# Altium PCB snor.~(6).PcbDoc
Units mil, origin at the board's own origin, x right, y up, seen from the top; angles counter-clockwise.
Board outline 6000 x 4000 mil, 2 copper layers (Top Layer, Bottom Layer); 54 components, 39 nets, 160 pads, 0 vias.
Unrouted connection lines stored in the file: 82.
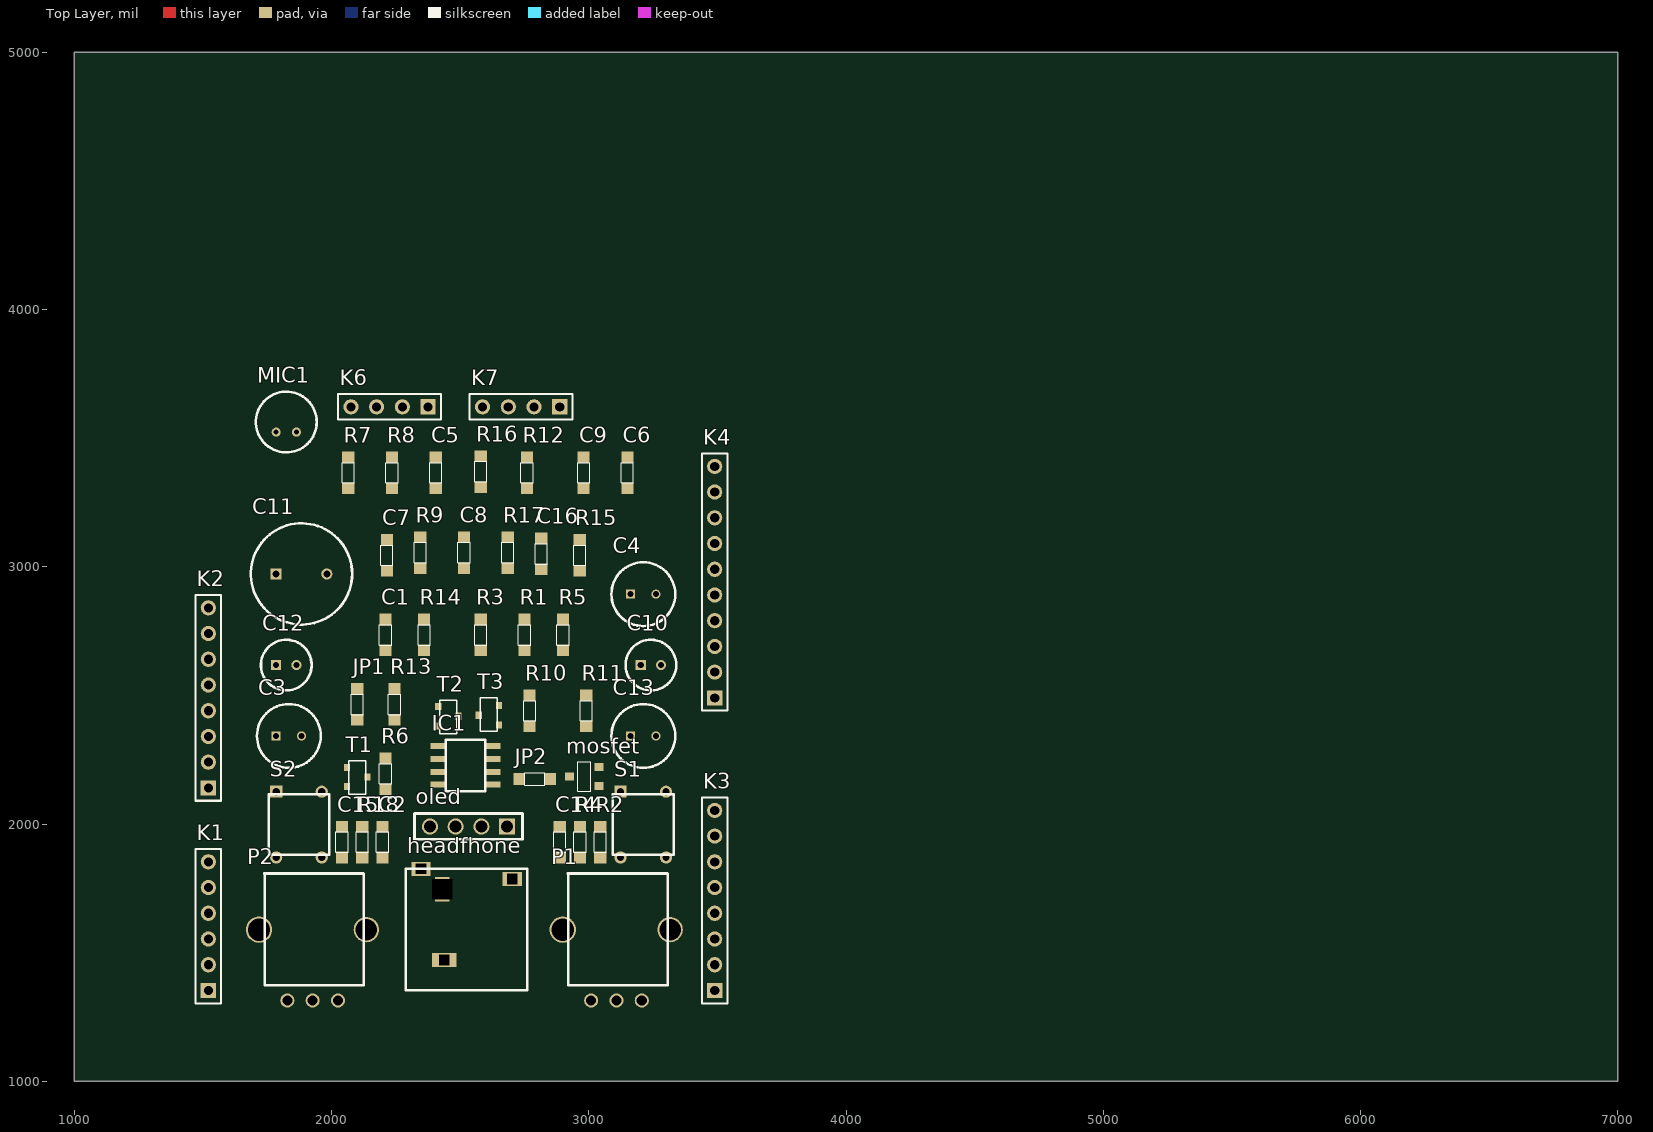
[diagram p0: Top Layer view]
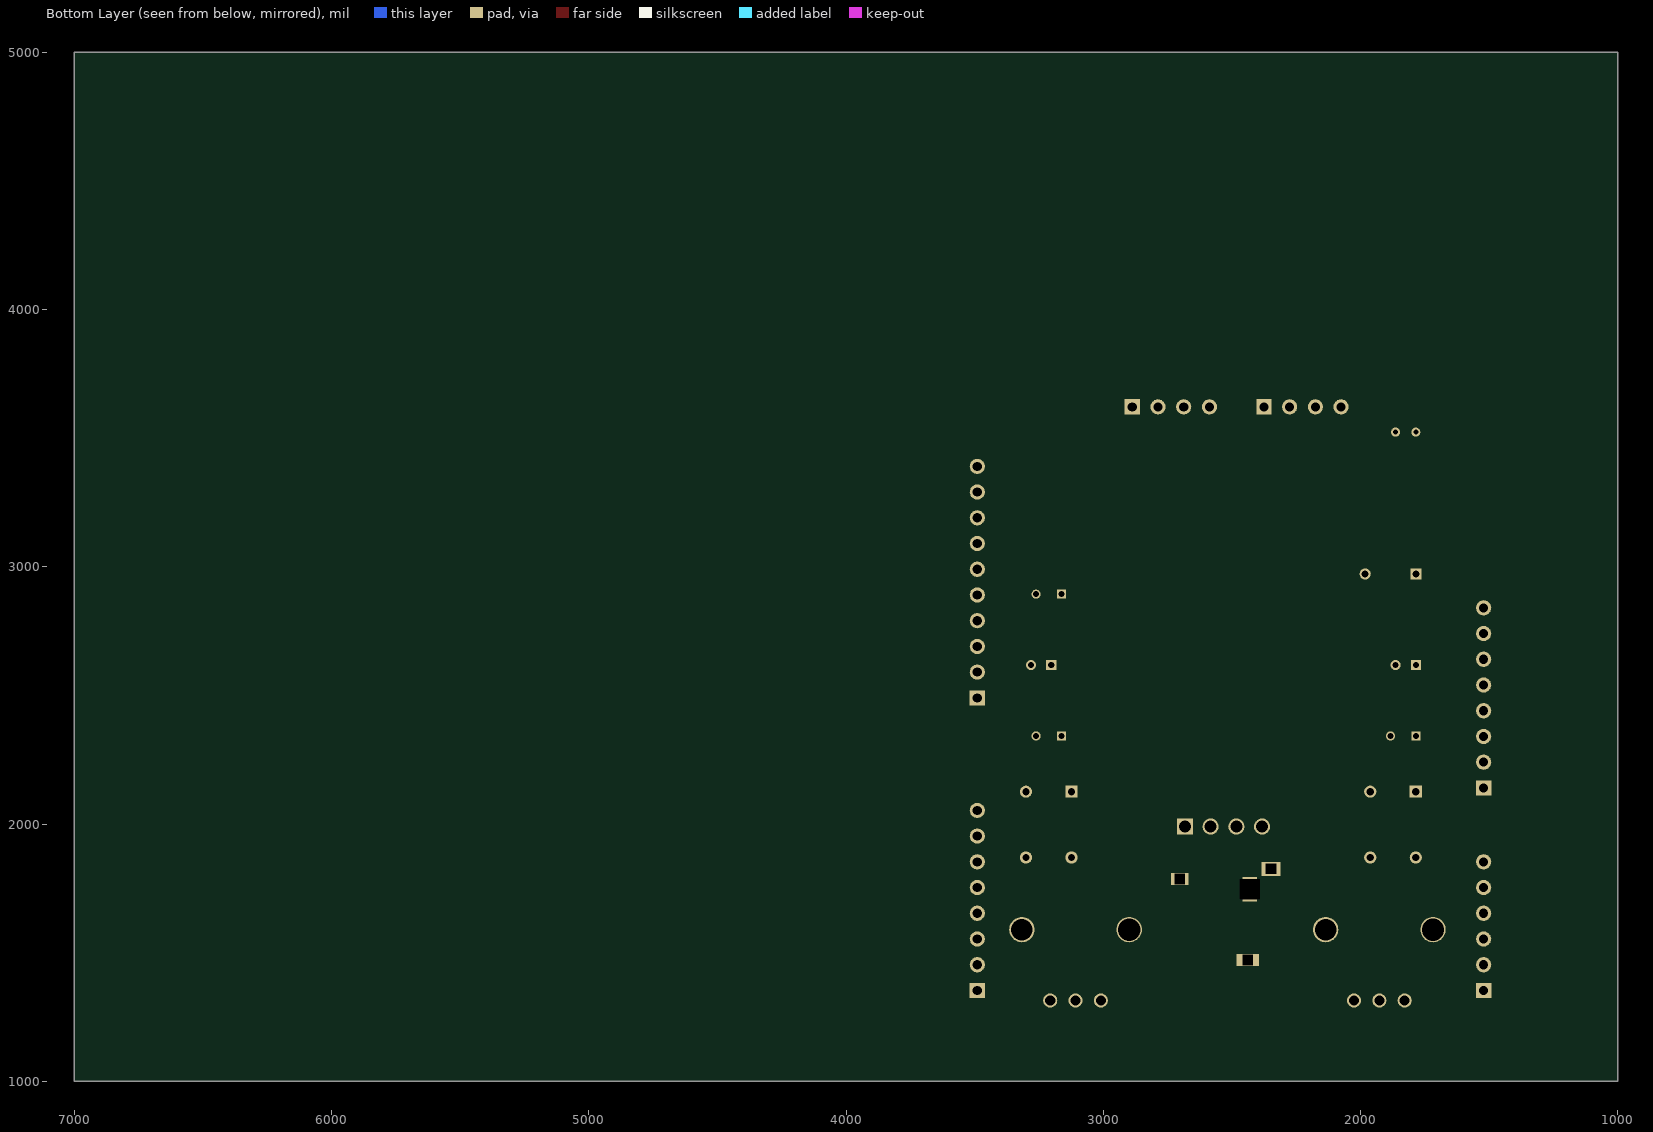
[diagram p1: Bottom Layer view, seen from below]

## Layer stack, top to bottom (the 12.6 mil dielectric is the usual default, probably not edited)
Top Solder: solder mask 0.4, Solder Resist, Dk 3.5
Top Layer: signal copper 1.4
Dielectric 1: dielectric 12.6, FR-4, Dk 4.8
Bottom Layer: signal copper 1.4
Bottom Solder: solder mask 0.4, Solder Resist, Dk 3.5

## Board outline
1000,1000 7000,1000 7000,5000 1000,5000

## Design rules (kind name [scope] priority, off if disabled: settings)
Clearance [All] p1: gap=10 ignorepadtopadclearanceinfootprint=FALSE except(0: Arc-Hole Track-Hole SMDPad-Hole THPad-Hole Via-Hole Fill-Hole Poly-Hole Region-Hole Text-Hole)
PolygonConnect [All] p1: connectstyle=Relief reliefconductorwidth=10 reliefentries=4 polygonreliefangle="90 Angle" airgapwidth=10
RoomDefinition snor_shield_sheet [InComponentClass('snor_shield_sheet')] p1: confinementstyle=ConfineIn formatcopy=TRUE lockcomponents=FALSE outline 8280,1385 21060,1385 21060,2505 8280,2505
RoutingVias [All] p1: holewidth=28 width=50 viastyle="Through Hole" minholewidth=28 minwidth=50 maxholewidth=28 maxwidth=50
SolderMaskExpansion [All] p1: expansion=4 istentingtop=FALSE
Width [All] p1: maxlimit=10 minlimit=10 preferedwidth=10
30 further rules are at their usual default settings.

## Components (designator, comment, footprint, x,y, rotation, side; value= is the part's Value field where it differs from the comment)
C1 "Capitor" "SMD 0805" 2210,2675 r90 top value=1µF
C2 "Capitor" "SMD 0805" 2198.19,1869.76 r90 top value=100nF
C3 "Cap Pol1" "elektor trans 2" 1784.8,2342.2 r0 top value=47µF/16V
C4 "Cap Pol1" "elektor trans 2" 3162.76,2893.39 r0 top value=47µF/16V
C5 "Capitor" "SMD 0805" 2405,3305 r90 top value=100pF
C6 "Capitor" "SMD 0805" 3150,3305 r90 top value=100pF
C7 "Capitor" "SMD 0805" 2215,2985 r90 top value=1nF
C8 "Capitor" "SMD 0805" 2515,2995 r90 top value=1µF
C9 "Capitor" "SMD 0805" 2980,3305 r90 top value=47nF
C10 "Cap Pol1" "elecktor trans 1" 3202.13,2617.8 r0 top value=10µF/16V
C11 "Cap Pol1" "elektor trans 3" 1784.8,2972.13 r0 top value=220µF/16V
C12 "Cap Pol1" "elecktor trans 1" 1784.8,2617.8 r0 top value=10µF/16V
C13 "Cap Pol1" "elektor trans 2" 3162.76,2342.2 r0 top value=47µF/16V
C14 "Cap" "SMD 0805" 2887.17,1869.76 r90 top value=100nF
C15 "Capitor" "SMD 0805" 2040.71,1869.76 r90 top value=100nF
C16 "Capitor" "SMD 0805" 2815,2990 r90 top value=100nF
headfhone "K-JACK-STEREO-3.5MM" adioplug3.5mm 2702.2,1786.02 r180 top
IC1 "LM386M-1/NOPB" LM386M-1/NOPB 2414.72,2302.83 r0 top
JP1 "Res2" "SMD 0805" 2100,2525.08 r270 top value=0Ohm
JP2 "Res2" "SMD 0805" 2850.08,2175 r180 top value=0Ohm
K1 "Header 6" HDR1X6 1521.1,1352.95 r90 top
K2 "Header 8" HDR1X8 1521.1,2140.35 r90 top
K3 "Header 8" HDR1X8 3489.61,1352.95 r90 top
K4 "Header 10" HDR1X10 3489.61,2490.35 r90 top
K6 "Header 4" HDR1X4 2375.35,3621.73 r180 top
K7 "Header 4" HDR1X4 2887.17,3621.73 r180 top
MIC1 "Mic2" "Electret Condenser Microphone" 1784.8,3523.31 r0 top
mosfet "power MOSFET" "power mosfet" 2925,2184.72 r90 top
oled "1X4 socked" "oled scherm" 2682.52,1990 r180 top
P1 "Res Adj2" potmeter 2899.06,1589.17 r0 top value=100k
P2 "Res Adj2" potmeter 1717.95,1589.17 r0 top value=10K
R1 "weerstand" "SMD 0805" 2750,2675 r90 top value=27K
R2 "weerstand" "SMD 0805" 3044.65,1869.76 r90 top value=15K
R3 "weerstand" "SMD 0805" 2580,2675 r90 top value=27K
R4 "weerstand" "SMD 0805" 2965.91,1869.76 r90 top value=1K2
R5 "weerstand" "SMD 0805" 2900,2675 r90 top value=10K
R6 "weerstand" "SMD 0805" 2210,2134.92 r90 top value=680Ohm
R7 "weerstand" "SMD 0805" 2065,3305 r90 top value=10K
R8 "weerstand" "SMD 0805" 2235,3305 r90 top value=10K
R9 "weerstand" "SMD 0805" 2345,2995 r90 top value=10K
R10 "weerstand" "SMD 0805" 2770,2380 r90 top value=180K
R11 "weerstand" "SMD 0805" 2990,2380 r90 top value=180K
R12 "weerstand" "SMD 0805" 2760,3305 r90 top value=10K
R13 "weerstand" "SMD 0805" 2245,2404.92 r90 top value=1K
R14 "weerstand" "SMD 0805" 2360,2675 r90 top value=100K
R15 "weerstand" "SMD 0805" 2965,2985 r90 top value=10Ohm
R16 "weerstand" "SMD 0805" 2580,3309.92 r90 top value=1K
R17 "Res2" "SMD 0805" 2685,2995 r90 top value=100K
R18 "weerstand" "SMD 0805" 2119.45,1869.76 r90 top value=10Ohm
S1 "SW-PB" switch 3123.39,2125.67 r0 top
S2 "SW-PB" switch 1784.8,2125.67 r0 top
T1 "BC847C" "bipolar BjT" 2060.39,2145.35 r90 top
T2 "BC847C" "bipolar BjT" 2414.72,2381.57 r90 top
T3 "BC847C" "bipolar BjT" 2650.94,2460.32 r270 top

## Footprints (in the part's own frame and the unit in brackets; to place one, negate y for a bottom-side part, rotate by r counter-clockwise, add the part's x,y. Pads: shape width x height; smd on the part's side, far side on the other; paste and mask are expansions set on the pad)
adioplug3.5mm [mm]
  rect 1.4x2.4 hole 2 square: B(6.9,1)
  rect 1.9x1.4 hole 1 square: R(9,-1)
  rect 2.4x1.4 / inner rect 2.2x1.27 / far side rect 2.2x1.2 hole 1 square: S(6.7,8)
  rect 1.9x1.4 / inner rect 2.54x1.27 / far side rect 1.7x1.2 hole 1 square: T(0,0)
  silkscreen extent -1.5,-1 10.5,11
"bipolar BjT" [mm]
  rect 0.7x0.6 smd: 1(0,0) 3(0.95,-2) 4(1.9,0)
  silkscreen extent -0.76,-1.85 2.54,-0.15
"elecktor trans 1" [mm]
  rect 1x1 hole 0.6: 1(0,0)
  round 1 hole 0.6: 2(2,0)
  silkscreen extent -1.5,-2.5 3.5,2.5
"Electret Condenser Microphone" [mm]
  round 0.9 hole 0.5: 1(0,0) 2(2,0)
  silkscreen extent -2,-2 4,4
"elektor trans 2" [mm]
  rect 0.9x0.9 hole 0.6: 1(0,0)
  round 0.9 hole 0.6: 2(2.5,0)
  silkscreen extent -1.9,-3.15 4.4,3.15
"elektor trans 3" [mm]
  rect 1.1x1.1 hole 0.7: 1(0,0)
  round 1.1 hole 0.7: 2(5,0)
  silkscreen extent -2.5,-5 7.5,5
HDR1X4 [mm] "Connector; Header; 4 Position"
  rect 1.5x1.5 hole 0.9: 1(0,0)
  round 1.5 hole 0.9: 2(2.54,0) 3(5.08,0) 4(7.62,0)
  silkscreen extent -1.27,-1.27 8.89,1.27
HDR1X6 [mm] "Connector; Header; 6 Position"
  rect 1.5x1.5 hole 0.9: 1(0,0)
  round 1.5 hole 0.9: 2(2.54,0) 3(5.08,0) 4(7.62,0) 5(10.16,0) 6(12.7,0)
  silkscreen extent -1.27,-1.27 13.97,1.27
HDR1X8 [mm] "Connector; Header; 8 Position"
  rect 1.5x1.5 hole 0.9: 1(0,0)
  round 1.5 hole 0.9: 2(2.54,0) 3(5.08,0) 4(7.62,0) 5(10.16,0) 6(12.7,0) 7(15.24,0) 8(17.78,0)
  silkscreen extent -1.27,-1.27 19.05,1.27
HDR1X10 [mm] "Connector; Header; 10 Position"
  rect 1.5x1.5 hole 0.9: 1(0,0)
  round 1.5 hole 0.9: 2(2.54,0) 3(5.08,0) 4(7.62,0) 5(10.16,0) 6(12.7,0) 7(15.24,0) 8(17.78,0) 9(20.32,0) 10(22.86,0)
  silkscreen extent -1.27,-1.27 24.13,1.27
LM386M-1/NOPB [mm]
  rect 1.55x0.6 smd: 1(0,0) 2(0,-1.27) 3(0,-2.54) 4(0,-3.81) 5(5.4,-3.81) 6(5.4,-2.54) 7(5.4,-1.27) 8(5.4,0)
  silkscreen extent 0.75,-4.44 4.65,0.64
"oled scherm" [mm]
  rect 1.6x1.6 hole 1.2: 1(0,0)
  round 1.6 hole 1.2: 2(5.08,0) 3(7.62,0) 4(2.54,0)
  silkscreen extent -1.52,-1.29 9.14,1.25
potmeter [mm]
  round 2.6 / inner round 2.5 / far side round 2.5 hole 2.2: 1(0,0)
  round 1.4 hole 1: 2(2.8,-7) 5(5.3,-7)
  round 1.4 / inner oval 1.4x0.064 / far side round 1.4 hole 1: 3(7.8,-7)
  round 2.5 / inner oval 2.5x0.064 / far side round 2.5 hole 2.1: 4(10.6,0)
  silkscreen extent 0.51,-5.5 10.35,5.55
"power mosfet" [mm]
  rect 0.8x0.9 smd: 1(0,0) 2(-0.95,-2.9) 3(0.95,-2.9)
  silkscreen extent -1.45,-2.1 1.45,-0.8
"SMD 0805" [mm]
  rect 1.14x1.2 smd: 1(0,0) 2(3.05,0)
  silkscreen extent 0.53,-0.6 2.53,0.6
switch [mm]
  rect 1.2x1.2 hole 0.71: 1(0,0)
  round 1.2 hole 0.71: 2(0,-6.5) 3(4.5,-6.5) 4(4.5,0)
  silkscreen extent -0.74,-6.25 5.25,-0.26

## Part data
C1 C2 C5 C6 C7 C8 C9 C15 C16: "Capacitor"
C3 C4 C13: library part "Cap Pol1_1", "Polarized Capacitor (Radial) 47µF"
C10 C12: "Polarized Capacitor (Radial) 10µF"
C11: library part "Cap Pol1_2", "Polarized Capacitor (Radial) 220µF"
C14: library part Capitor, "Capacitor"
JP1 JP2: library part solderjump, "Resistor"
K1: "Header, 6-Pin"
K2 K3: "Header, 8-Pin"
K4: "Header, 10-Pin"
K6: "Header, 4-Pin"
K7: "Header, 4-Pin,2mm"
MIC1: "Microphone"
P1: "Variable Resistor 10K"
P2: library part "Res Adj2_1", "Variable Resistor"
R1 R2 R3 R4 R5 R6 R7 R8 R9 R10 R11 R12 R13 R14 R15 R16 R18: "Resistor"
R17: library part weerstand, "Resistor"
S1 S2: library part switch, "Switch"
T1 T2 T3: library part BJT, "NPN General Purpose Amplifier"

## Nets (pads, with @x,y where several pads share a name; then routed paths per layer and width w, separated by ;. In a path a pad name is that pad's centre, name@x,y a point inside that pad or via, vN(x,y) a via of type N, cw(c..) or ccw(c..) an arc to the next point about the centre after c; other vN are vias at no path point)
+5V: C13.1 C14.2 IC1.6 R1.2 R3.2 R5.2 R18.2
GND: C2.1 C3.1 C4.2 C5.1 C12.2 C13.2 C14.1 C15.1 C16.1 IC1.2 IC1.4 K2.6 K2.7 K4.7 K6.4 K7.1 MIC1.1 P2.1 R2.1 R4.1 R12.1 R14.1 R15.1 S1.1 S2.1 T2.1
NetC1_1: C1.1 MIC1.2 R5.1
NetC1_2: C1.2 R6.1
NetC2_2: C2.2 R1.1 R2.2 R6.2
NetC3_2: C3.2 R4.2 T1.1
NetC4_1: C4.1 C16.2 R7.2 R9.2 R13.2
NetC5_2: C5.2 R11.1
NetC6_1: C6.1 C8.1 P1.1 R12.2 T3.1
NetC6_2: C6.2 C7.2 R10.1 R11.2
NetC7_1: C7.1 P1.3
NetC8_2: C8.2 R17.2
NetC9_1: C9.1 R15.2
NetC9_2: C9.2 C11.1 IC1.5
NetC10_1: C10.1 R16.2
NetC10_2: C10.2 IC1.8
NetC11_2: C11.2
NetC12_1: C12.1 IC1.7
NetC15_2: C15.2 K2.1 K6.3 K7.2 R18.1
NetIC1_1: IC1.1 R16.1
NetIC1_3: IC1.3 P2.3
NetJP1_14: oled.2
NetJP1_17: 
NetJP2_14: oled.1
NetK1_1: K1.1 R3.1 T1.3
NetK1_5: K1.5 oled.4
NetK1_6: K1.6 oled.3
NetK3_3: K3.3 K6.1 K7.4
NetK3_4: K3.4 K6.2 K7.3
NetK3_6: K3.6 S1.2
NetK3_7: K3.7 R7.1
NetK3_8: K3.8 S2.2
NetK4_1: K4.1 R8.1
NetK4_2: K4.2 R14.2
Netmosfet_6: P1.2
NetP2_2: P2.2 R17.1
NetR8_2: R8.2
NetR9_1: R9.1 R10.2 T2.3
NetR13_1: R13.1 T3.3
pads on no net: headfhone.B headfhone.R headfhone.S headfhone.T JP1.1 JP1.2 JP2.1 JP2.2 K1.2 K1.3 K1.4 K2.2 K2.3 K2.4 K2.5 K2.8 K3.1 K3.2 K3.5 K4.3 K4.4 K4.5 K4.6 K4.8 K4.9 K4.10 mosfet.1 mosfet.2 mosfet.3 P1.4 P1.5 P2.4 P2.5 S1.3 S1.4 S2.3 S2.4 T1.4 T2.4 T3.4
